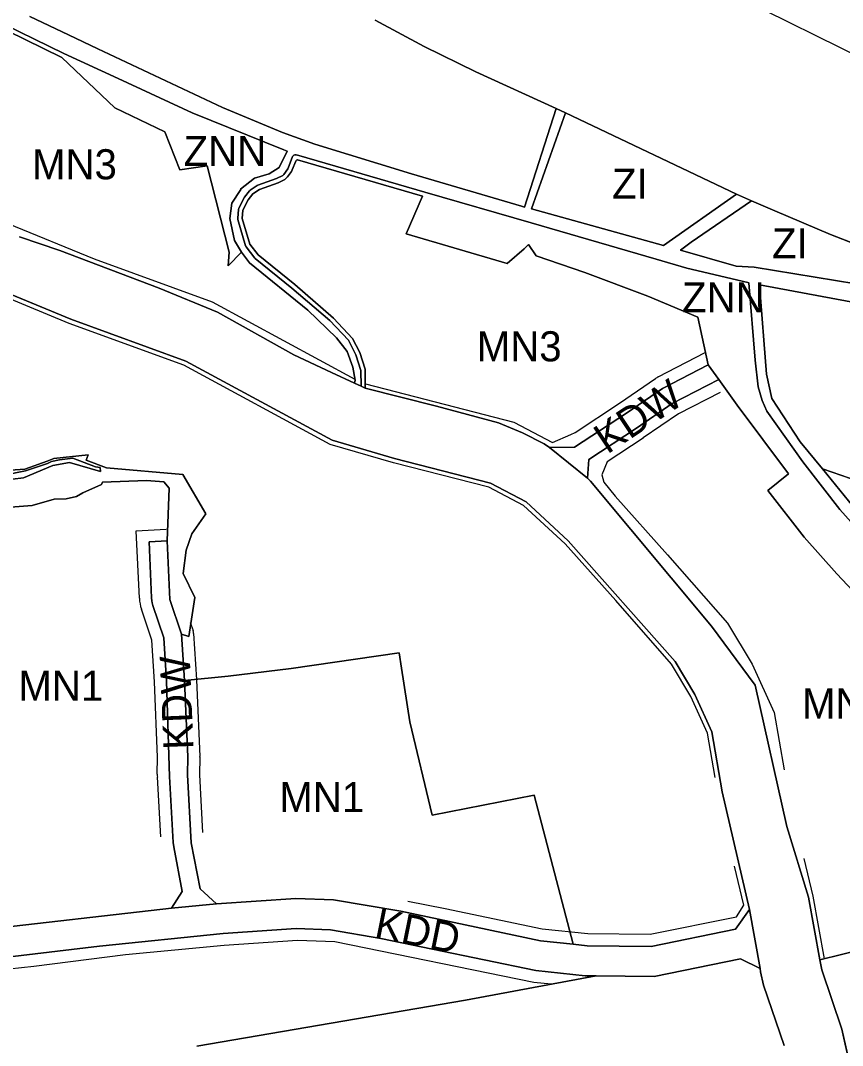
# Model space of a CAD drawing. Extents: x 7417187 to 7419415, y 5539178 to 5540826.
# Drawn here: x 7417955.3 to 7418228.7, y 5540197.8 to 5540538.4 of the extents above; entities that cross this region are included whole.
import ezdxf

# ---------------------------------------------------------------- set-up
doc = ezdxf.new("R2010")
doc.units = 0
for name, color, linetype in [('linie_rozgraniczajace', 7, 'Continuous'), ('linie_zabudowy_nieprzekraczalne', 7, 'Continuous'), ('linie_zabudowy_obowiazujace', 7, 'Continuous'), ('oznaczenia_przeznaczen', 7, 'Continuous')]:
    doc.layers.add(name, color=color, linetype=linetype)

msp = doc.modelspace()

# ---------------------------------------------------------------- linework, layer by layer
at = {"layer": 'linie_rozgraniczajace'}
for p, q in [((7418184.51, 5540550.92), (7418276.66, 5540505.27)), ((7418089.52, 5540529.78), (7418073.23, 5540538.56)), ((7418106.7, 5540521.4), (7418089.52, 5540529.78)), ((7418133.47, 5540509.15), (7418106.7, 5540521.4)), ((7418136.49, 5540507.76), (7418133.47, 5540509.15)), ((7418193.46, 5540480.73), (7418136.49, 5540507.76)), ((7418198.39, 5540478.49), (7418193.46, 5540480.73)), ((7418206.14, 5540475.18), (7418198.39, 5540478.49)), ((7418224.72, 5540467.32), (7418206.14, 5540475.18)), ((7417954.91, 5540466.53), (7417968.32, 5540461.96)), ((7418250.22, 5540457.36), (7418224.72, 5540467.32)), ((7417968.32, 5540461.96), (7418001.44, 5540449.44)), ((7417972.03, 5540439.13), (7417941.88, 5540451.55)), ((7418001.44, 5540449.44), (7418020.76, 5540441.54)), ((7418203.41, 5540420.94), (7418201.06, 5540450.58)), ((7418201.06, 5540450.58), (7418231.46, 5540444.97)), ((7418010.24, 5540425.25), (7417972.03, 5540439.13)), ((7418020.76, 5540441.54), (7418046.17, 5540427.29)), ((7418046.17, 5540427.29), (7418058.73, 5540421.49)), ((7418058.9, 5540398.92), (7418010.24, 5540425.25)), ((7418058.73, 5540421.49), (7418066.38, 5540417.89)), ((7418205.11, 5540412.77), (7418203.41, 5540420.94)), ((7418066.38, 5540417.89), (7418068.6, 5540416.85)), ((7418068.6, 5540416.85), (7418069.96, 5540416.21)), ((7418069.96, 5540416.21), (7418093.68, 5540410.23)), ((7418214.63, 5540398.45), (7418205.11, 5540412.77)), ((7418093.68, 5540410.23), (7418114.25, 5540404.75)), ((7418114.25, 5540404.75), (7418122.23, 5540401.34)), ((7418079.69, 5540392.91), (7418058.9, 5540398.92)), ((7418122.23, 5540401.34), (7418129.46, 5540397.73)), ((7418221.99, 5540389.44), (7418214.63, 5540398.45)), ((7418129.46, 5540397.73), (7418131.26, 5540396.56)), ((7418131.26, 5540396.56), (7418143.87, 5540386.28)), ((7418111.56, 5540384.71), (7418079.69, 5540392.91)), ((7418568.33, 5540270.22), (7418221.99, 5540389.44)), ((7418123.42, 5540378.5), (7418111.56, 5540384.71)), ((7418143.87, 5540386.28), (7418144.87, 5540385.36)), ((7418144.87, 5540385.36), (7418185.06, 5540337.16)), ((7418137.46, 5540365.56), (7418123.42, 5540378.5)), ((7418172.97, 5540325.41), (7418137.46, 5540365.56)), ((7418185.06, 5540337.16), (7418199.57, 5540317.59)), ((7418179.58, 5540314.47), (7418172.97, 5540325.41)), ((7418199.57, 5540317.59), (7418210.2, 5540270.52)), ((7418185.22, 5540302.05), (7418179.58, 5540314.47)), ((7418188.69, 5540282.1), (7418185.22, 5540302.05)), ((7418197.7, 5540242.96), (7418188.69, 5540282.1)), ((7418210.2, 5540270.52), (7418217.35, 5540247.1)), ((7418217.35, 5540247.1), (7418221.14, 5540226.27)), ((7418201.23, 5540223.35), (7418197.7, 5540242.96)), ((7418221.14, 5540226.27), (7418221.74, 5540222.95)), ((7418201.42, 5540222.28), (7418201.23, 5540223.35)), ((7418202.33, 5540217.9), (7418201.42, 5540222.28)), ((7418221.74, 5540222.95), (7418228.49, 5540203.2)), ((7418209.21, 5540197.77), (7418202.33, 5540217.9)), ((7418228.49, 5540203.2), (7418234.02, 5540178.42))]:
    msp.add_line(p, q, dxfattribs=at)
for points in [[(7417945.14, 5540539.44), (7417969.74, 5540527.46), (7417987.79, 5540519.1), (7418012.43, 5540507.77), (7418042.85, 5540495.44), (7418043.98, 5540494.99), (7418041.28, 5540489.53), (7418037.97, 5540487.48), (7418033.07, 5540486), (7418028.48, 5540482.4), (7418028.54, 5540482.27), (7418025.59, 5540477.67), (7418024.93, 5540472.63), (7418026.44, 5540465.3), (7418028.76, 5540461.43), (7418024.37, 5540456.87), (7418024.64, 5540461.41), (7418017.37, 5540490.07), (7418008.26, 5540488.82), (7418003.24, 5540501.47), (7417986.61, 5540509.43), (7417969.09, 5540526.11), (7417944.77, 5540538.03), (7417931.33, 5540544.79)], [(7417944.77, 5540538.03), (7417969.09, 5540526.11), (7417986.61, 5540509.43), (7418003.24, 5540501.47), (7418008.26, 5540488.82), (7418017.37, 5540490.07), (7418024.64, 5540461.41), (7418024.37, 5540456.87), (7418028.76, 5540461.43), (7418031.49, 5540457.9), (7418050.88, 5540442.16), (7418060.36, 5540432.97), (7418063.92, 5540428.39), (7418065.8, 5540423.21), (7418066.58, 5540418.89), (7418066.38, 5540417.89), (7418058.73, 5540421.49), (7418046.17, 5540427.29), (7418020.76, 5540441.54), (7418001.44, 5540449.44), (7417968.32, 5540461.96), (7417954.91, 5540466.53)], [(7418237.98, 5540364.53), (7418227.82, 5540375.89), (7418215.42, 5540391.72), (7418203.51, 5540408.65), (7418201.91, 5540412.14), (7418200.64, 5540416.69), (7418199.58, 5540425.52), (7418197.49, 5540451.24), (7418197.18, 5540451.32), (7418176.94, 5540456.17), (7418166.7, 5540459.13), (7418125.11, 5540471.15), (7418089.75, 5540481.34), (7418047.83, 5540493.52), (7418047, 5540493.76), (7418046.77, 5540493.8), (7418046.51, 5540493.78), (7418046.22, 5540493.67), (7418046, 5540493.49), (7418045.88, 5540493.33), (7418045.8, 5540493.17), (7418044.27, 5540489.34), (7418044.16, 5540489.14), (7418042.87, 5540487.27), (7418042.8, 5540487.17), (7418042.64, 5540487.03), (7418042.51, 5540486.95), (7418040.47, 5540485.89), (7418034.18, 5540483.69), (7418033.96, 5540483.57), (7418031.63, 5540482.01), (7418031.4, 5540481.8), (7418029.8, 5540479.76), (7418029.69, 5540479.59), (7418027.87, 5540475.95), (7418027.79, 5540475.73), (7418027.77, 5540475.58), (7418027.53, 5540472.69), (7418027.53, 5540472.48), (7418027.56, 5540472.32), (7418030.17, 5540463.59), (7418030.2, 5540463.5), (7418030.23, 5540463.42), (7418030.28, 5540463.33), (7418030.34, 5540463.26), (7418033.27, 5540459.48), (7418033.38, 5540459.37), (7418045.55, 5540449.47), (7418058.12, 5540438.7), (7418064.36, 5540432.18), (7418066.85, 5540427.35), (7418068.43, 5540422.14), (7418068.6, 5540416.85), (7418066.38, 5540417.89), (7418066.58, 5540418.89), (7418065.8, 5540423.21), (7418063.92, 5540428.39), (7418060.36, 5540432.97), (7418050.88, 5540442.16), (7418031.49, 5540457.9), (7418028.76, 5540461.43), (7418026.44, 5540465.3), (7418024.93, 5540472.63), (7418025.59, 5540477.67), (7418028.54, 5540482.27), (7418028.48, 5540482.4), (7418033.07, 5540486), (7418037.97, 5540487.48), (7418041.28, 5540489.53), (7418043.98, 5540494.99), (7418042.85, 5540495.44), (7418012.43, 5540507.77), (7417987.79, 5540519.1), (7417969.74, 5540527.46), (7417945.14, 5540539.44)], [(7417958.44, 5540539.73), (7417971.26, 5540533.63), (7417981.02, 5540529.03), (7418022.49, 5540509.53), (7418042.39, 5540501.23), (7418053.23, 5540497.36), (7418085.3, 5540487.44), (7418121.92, 5540476.69), (7418122.9, 5540476.44), (7418133.47, 5540509.15), (7418136.49, 5540507.76), (7418125.23, 5540475.82), (7418169.18, 5540463.68), (7418193.46, 5540480.73), (7418198.39, 5540478.49), (7418178.36, 5540464.75), (7418174.76, 5540462.14), (7418193.33, 5540456.73), (7418199.26, 5540456.48), (7418233.05, 5540450.86)], [(7418073.23, 5540538.56), (7418089.52, 5540529.78), (7418106.7, 5540521.4), (7418133.47, 5540509.15), (7418122.9, 5540476.44), (7418121.92, 5540476.69), (7418085.3, 5540487.44), (7418053.23, 5540497.36), (7418042.39, 5540501.23), (7418022.49, 5540509.53), (7417981.02, 5540529.03), (7417971.26, 5540533.63), (7417958.44, 5540539.73)], [(7418253.06, 5540326.64), (7418226.81, 5540354.53), (7418215.96, 5540366.69), (7418203.79, 5540382.24), (7418210.66, 5540387.82), (7418193.67, 5540410.56), (7418187.52, 5540419.09), (7418184, 5540424.02), (7418180.55, 5540439.82), (7418163.87, 5540446.84), (7418143, 5540454.69), (7418126.77, 5540460.16), (7418124.24, 5540463.97), (7418122.74, 5540462.55), (7418117.16, 5540457.62), (7418083.59, 5540467.54), (7418088.97, 5540480.04), (7418047.41, 5540492.08), (7418047.25, 5540492.09), (7418047.07, 5540492.02), (7418046.92, 5540491.89), (7418046.83, 5540491.71), (7418045.66, 5540488.78), (7418045.4, 5540488.29), (7418044.11, 5540486.42), (7418043.2, 5540485.61), (7418041.16, 5540484.56), (7418040.96, 5540484.47), (7418034.74, 5540482.3), (7418032.53, 5540480.81), (7418031.01, 5540478.87), (7418029.26, 5540475.36), (7418029.03, 5540472.66), (7418031.58, 5540464.1), (7418034.37, 5540460.51), (7418046.5, 5540450.64), (7418059.43, 5540439.55), (7418065.75, 5540432.76), (7418068.19, 5540428.04), (7418069.87, 5540422.58), (7418069.93, 5540422.19), (7418069.96, 5540416.21), (7418068.6, 5540416.85), (7418068.43, 5540422.14), (7418066.85, 5540427.35), (7418064.36, 5540432.18), (7418058.12, 5540438.7), (7418045.55, 5540449.47), (7418033.38, 5540459.37), (7418033.27, 5540459.48), (7418030.34, 5540463.26), (7418030.28, 5540463.33), (7418030.23, 5540463.42), (7418030.2, 5540463.5), (7418030.17, 5540463.59), (7418027.56, 5540472.32), (7418027.53, 5540472.48), (7418027.53, 5540472.69), (7418027.77, 5540475.58), (7418027.79, 5540475.73), (7418027.87, 5540475.95), (7418029.69, 5540479.59), (7418029.8, 5540479.76), (7418031.4, 5540481.8), (7418031.63, 5540482.01), (7418033.96, 5540483.57), (7418034.18, 5540483.69), (7418040.47, 5540485.89), (7418042.51, 5540486.95), (7418042.64, 5540487.03), (7418042.8, 5540487.17), (7418042.87, 5540487.27), (7418044.16, 5540489.14), (7418044.27, 5540489.34), (7418045.8, 5540493.17), (7418045.88, 5540493.33), (7418046, 5540493.49), (7418046.22, 5540493.67), (7418046.51, 5540493.78), (7418046.77, 5540493.8), (7418047, 5540493.76), (7418047.83, 5540493.52), (7418089.75, 5540481.34), (7418125.11, 5540471.15), (7418166.7, 5540459.13), (7418176.94, 5540456.17), (7418197.18, 5540451.32), (7418197.49, 5540451.24), (7418199.58, 5540425.52), (7418200.64, 5540416.69), (7418201.91, 5540412.14), (7418203.51, 5540408.65), (7418215.42, 5540391.72), (7418227.82, 5540375.89), (7418237.98, 5540364.53)], [(7417941.88, 5540451.55), (7417972.03, 5540439.13), (7418010.24, 5540425.25), (7418058.9, 5540398.92), (7418079.69, 5540392.91), (7418111.56, 5540384.71), (7418123.42, 5540378.5), (7418137.46, 5540365.56), (7418172.97, 5540325.41), (7418179.58, 5540314.47), (7418185.22, 5540302.05), (7418188.69, 5540282.1), (7418197.7, 5540242.96), (7418193.07, 5540236.44), (7418165.06, 5540230.74), (7418143.69, 5540230.97), (7418139.13, 5540231.45), (7418126.13, 5540281), (7418092.21, 5540274.34), (7418084.77, 5540305.35), (7418082.04, 5540323.19), (7418081.27, 5540328.34), (7418045.29, 5540323.12), (7418024.34, 5540320.55), (7418009.86, 5540319.08), (7418008.88, 5540334.46), (7418011.3, 5540333.72), (7418013.28, 5540346.63), (7418009.37, 5540354.65), (7418010.34, 5540362.43), (7418012.27, 5540367.82), (7418016.98, 5540374.46), (7418009.32, 5540387.6), (7417983.86, 5540389.74), (7417977.17, 5540392.31), (7417977.79, 5540394.13), (7417966.38, 5540392.86), (7417964.16, 5540391.99), (7417956.78, 5540389.28), (7417948.8, 5540388.78)], [(7418231.46, 5540444.97), (7418201.06, 5540450.58), (7418203.41, 5540420.94), (7418205.11, 5540412.77), (7418214.63, 5540398.45), (7418221.99, 5540389.44), (7418235.03, 5540373.5)], [(7418235.5, 5540229.77), (7418221.14, 5540226.27), (7418217.35, 5540247.1), (7418210.2, 5540270.52), (7418199.57, 5540317.59), (7418185.06, 5540337.16), (7418144.87, 5540385.36), (7418143.87, 5540386.28), (7418144.29, 5540392.55), (7418160.16, 5540402.99), (7418172.05, 5540411.13), (7418187.52, 5540419.09), (7418193.67, 5540410.56), (7418210.66, 5540387.82), (7418203.79, 5540382.24), (7418215.96, 5540366.69), (7418226.81, 5540354.53), (7418253.06, 5540326.64)], [(7417948.8, 5540388.78), (7417956.78, 5540389.28), (7417964.16, 5540391.99), (7417966.38, 5540392.86), (7417977.79, 5540394.13), (7417977.17, 5540392.31), (7417983.86, 5540389.74), (7418009.32, 5540387.6), (7418016.98, 5540374.46), (7418012.27, 5540367.82), (7418010.34, 5540362.43), (7418009.37, 5540354.65), (7418013.28, 5540346.63), (7418011.3, 5540333.72), (7418008.88, 5540334.46), (7418004.97, 5540345.99), (7418004.08, 5540365.45), (7418004.77, 5540383), (7418002.97, 5540385.08), (7417997.21, 5540385.56), (7417982.61, 5540384.97), (7417982.26, 5540384.26), (7417976.05, 5540381.43), (7417973.97, 5540380.19), (7417970.52, 5540379.47), (7417966.47, 5540379.3), (7417959.21, 5540377.27), (7417950.55, 5540376.53)], [(7417949.83, 5540387.35), (7417956.94, 5540388.72), (7417964.23, 5540391.24), (7417965.64, 5540391.82), (7417968.27, 5540392.44), (7417972.69, 5540392.96), (7417980.27, 5540390.05), (7417981.75, 5540389.92), (7417981.88, 5540388.54), (7417971.57, 5540391.49), (7417966.02, 5540390.49), (7417956.24, 5540386.4), (7417949.01, 5540385.55)], [(7417949.01, 5540385.55), (7417956.24, 5540386.4), (7417966.02, 5540390.49), (7417971.57, 5540391.49), (7417981.88, 5540388.54), (7417981.75, 5540389.92), (7417980.27, 5540390.05), (7417972.69, 5540392.96), (7417968.27, 5540392.44), (7417965.64, 5540391.82), (7417964.23, 5540391.24), (7417956.94, 5540388.72), (7417949.83, 5540387.35)], [(7418235.03, 5540373.5), (7418221.99, 5540389.44), (7418568.33, 5540270.22)], [(7417950.55, 5540376.53), (7417959.21, 5540377.27), (7417966.47, 5540379.3), (7417970.52, 5540379.47), (7417973.97, 5540380.19), (7417976.05, 5540381.43), (7417982.26, 5540384.26), (7417982.61, 5540384.97), (7417997.21, 5540385.56), (7418002.97, 5540385.08), (7418004.77, 5540383), (7418004.08, 5540365.45), (7417998.07, 5540365.21), (7417998.82, 5540346.59), (7417998.92, 5540345.57), (7417999.06, 5540344.87), (7417999.29, 5540344.07), (7418002.94, 5540333.29), (7418003.86, 5540318.84), (7418004.79, 5540287.17), (7418006.03, 5540265.31), (7418006.26, 5540263.77), (7418009.07, 5540248.98), (7418005.47, 5540243.42), (7417941.39, 5540236.16)], [(7417941.39, 5540236.16), (7418005.47, 5540243.42), (7418020.52, 5540244.86), (7418046.89, 5540246.66), (7418059.4, 5540246.2), (7418081.8, 5540242.41), (7418128.19, 5540232.61), (7418139.13, 5540231.45), (7418143.69, 5540230.97), (7418165.06, 5540230.74), (7418193.07, 5540236.44), (7418197.7, 5540242.96), (7418201.23, 5540223.35), (7418194.77, 5540226.58), (7418166.01, 5540220.73), (7418146.77, 5540220.94), (7418143.11, 5540220.98), (7418126.64, 5540222.72), (7418075.08, 5540233.41), (7418058.38, 5540236.24), (7418046.99, 5540236.65), (7418022.74, 5540235), (7417981.56, 5540230.85), (7417950.9, 5540227.13)], [(7417950.9, 5540227.13), (7417981.56, 5540230.85), (7418022.74, 5540235), (7418046.99, 5540236.65), (7418058.38, 5540236.24), (7418075.08, 5540233.41), (7418126.64, 5540222.72), (7418143.11, 5540220.98), (7418146.77, 5540220.94), (7418103.26, 5540212.86), (7418013.89, 5540197.63)], [(7418234.02, 5540178.42), (7418228.49, 5540203.2), (7418221.74, 5540222.95), (7418221.14, 5540226.27), (7418235.5, 5540229.77)], [(7418013.89, 5540197.63), (7418103.26, 5540212.86), (7418146.77, 5540220.94), (7418166.01, 5540220.73), (7418194.77, 5540226.58), (7418201.23, 5540223.35), (7418201.42, 5540222.28), (7418202.33, 5540217.9), (7418209.21, 5540197.77)]]:
    msp.add_lwpolyline(points, dxfattribs=at)
for points in [[(7418193.46, 5540480.73), (7418169.18, 5540463.68), (7418125.23, 5540475.82), (7418136.49, 5540507.76)], [(7418184, 5540424.02), (7418168.77, 5540416.15), (7418156.79, 5540407.96), (7418139.51, 5540396.59), (7418131.26, 5540396.56), (7418129.46, 5540397.73), (7418122.23, 5540401.34), (7418114.25, 5540404.75), (7418093.68, 5540410.23), (7418069.96, 5540416.21), (7418069.93, 5540422.19), (7418069.87, 5540422.58), (7418068.19, 5540428.04), (7418065.75, 5540432.76), (7418059.43, 5540439.55), (7418046.5, 5540450.64), (7418034.37, 5540460.51), (7418031.58, 5540464.1), (7418029.03, 5540472.66), (7418029.26, 5540475.36), (7418031.01, 5540478.87), (7418032.53, 5540480.81), (7418034.74, 5540482.3), (7418040.96, 5540484.47), (7418041.16, 5540484.56), (7418043.2, 5540485.61), (7418044.11, 5540486.42), (7418045.4, 5540488.29), (7418045.66, 5540488.78), (7418046.83, 5540491.71), (7418046.92, 5540491.89), (7418047.07, 5540492.02), (7418047.25, 5540492.09), (7418047.41, 5540492.08), (7418088.97, 5540480.04), (7418083.59, 5540467.54), (7418117.16, 5540457.62), (7418122.74, 5540462.55), (7418124.24, 5540463.97), (7418126.77, 5540460.16), (7418143, 5540454.69), (7418163.87, 5540446.84), (7418180.55, 5540439.82)], [(7418275.89, 5540448.03), (7418272.05, 5540447.47), (7418267.29, 5540447.39), (7418253.23, 5540448.9), (7418233.05, 5540450.86), (7418199.26, 5540456.48), (7418193.33, 5540456.73), (7418174.76, 5540462.14), (7418178.36, 5540464.75), (7418198.39, 5540478.49), (7418206.14, 5540475.18), (7418224.72, 5540467.32), (7418250.22, 5540457.36)], [(7418187.52, 5540419.09), (7418172.05, 5540411.13), (7418160.16, 5540402.99), (7418144.29, 5540392.55), (7418143.87, 5540386.28), (7418131.26, 5540396.56), (7418139.51, 5540396.59), (7418156.79, 5540407.96), (7418168.77, 5540416.15), (7418184, 5540424.02)], [(7418008.88, 5540334.46), (7418009.86, 5540319.08), (7418010.89, 5540293.69), (7418010.78, 5540287.74), (7418012.1, 5540265.14), (7418015.04, 5540249.87), (7418020.52, 5540244.86), (7418005.47, 5540243.42), (7418009.07, 5540248.98), (7418006.26, 5540263.77), (7418006.03, 5540265.31), (7418004.79, 5540287.17), (7418003.86, 5540318.84), (7418002.94, 5540333.29), (7417999.29, 5540344.07), (7417999.06, 5540344.87), (7417998.92, 5540345.57), (7417998.82, 5540346.59), (7417998.07, 5540365.21), (7418004.08, 5540365.45), (7418004.97, 5540345.99)], [(7418139.13, 5540231.45), (7418128.19, 5540232.61), (7418081.8, 5540242.41), (7418059.4, 5540246.2), (7418046.89, 5540246.66), (7418020.52, 5540244.86), (7418015.04, 5540249.87), (7418012.1, 5540265.14), (7418010.78, 5540287.74), (7418010.89, 5540293.69), (7418009.86, 5540319.08), (7418024.34, 5540320.55), (7418045.29, 5540323.12), (7418081.27, 5540328.34), (7418082.04, 5540323.19), (7418084.77, 5540305.35), (7418092.21, 5540274.34), (7418126.13, 5540281)]]:
    msp.add_lwpolyline(points, close=True, dxfattribs=at)
at = {"layer": 'linie_zabudowy_nieprzekraczalne'}
msp.add_line((7418162.42, 5540399.69), (7418162.32, 5540399.63), dxfattribs=at)
for points in [[(7418186.34, 5540286.9), (7418183.78, 5540301.6), (7418178.26, 5540313.77), (7418171.76, 5540324.53), (7418153.24, 5540345.66), (7418136.4, 5540364.51), (7418122.55, 5540377.27), (7418111.02, 5540383.3), (7418079.3, 5540391.47), (7418058.33, 5540397.52), (7418009.62, 5540423.88), (7417971.49, 5540437.73), (7417941.24, 5540450.2), (7417899.2, 5540472.95), (7417859.44, 5540494.09), (7417832.88, 5540506.56), (7417829.33, 5540508.1)], [(7417895.18, 5540501.14), (7417910.07, 5540493.22), (7417951.12, 5540471), (7417979.8, 5540459.18), (7418019.07, 5540444.92), (7418066.51, 5540419.25)], [(7418167.37, 5540419.96), (7418183.02, 5540428.09)], [(7418139.79, 5540401.5), (7418154.55, 5540411.27), (7418166.51, 5540419.45)], [(7418069.99, 5540417.64), (7418119.33, 5540404.91), (7418132.18, 5540398.19)], [(7418188.02, 5540414.85), (7418174.11, 5540407.69), (7418162.42, 5540399.69)], [(7418132.18, 5540398.19), (7418138.36, 5540400.85), (7418139.79, 5540401.5)], [(7418162.32, 5540399.63), (7418150.39, 5540391.72)], [(7418150.39, 5540391.72), (7418148.66, 5540387.47), (7418149.31, 5540384.95), (7418153.06, 5540380.37)], [(7418153.06, 5540380.37), (7418170.46, 5540360.9), (7418190.39, 5540338.16), (7418198.64, 5540324.51), (7418205.94, 5540308.44), (7418209.25, 5540289.36)], [(7418215.84, 5540259.9), (7418218.82, 5540247.41), (7418222.6, 5540226.63)], [(7418195.88, 5540244.48), (7418192.79, 5540257.42)], [(7418084.12, 5540245.75), (7418096.49, 5540243.27), (7418128.81, 5540236.57), (7418143.93, 5540234.97)], [(7418193.38, 5540240.59), (7418195.88, 5540244.48)], [(7418143.93, 5540234.97), (7418164.68, 5540234.74), (7418193.38, 5540240.59)], [(7418047.42, 5540232.67), (7418022.98, 5540231.01)], [(7418059.83, 5540232.26), (7418047.42, 5540232.67)], [(7418126.02, 5540218.77), (7418059.83, 5540232.26)], [(7417990.25, 5540227.91), (7417959.74, 5540224.09)], [(7418022.98, 5540231.01), (7417990.25, 5540227.91)], [(7417959.74, 5540224.09), (7417935.05, 5540221.41)], [(7418131.82, 5540218.16), (7418126.02, 5540218.77)]]:
    msp.add_lwpolyline(points, dxfattribs=at)
msp.add_arc((7418171.69, 5540411.85), 9.2, 118.0285, 124.2901, dxfattribs=at)
at = {"layer": 'linie_zabudowy_obowiazujace'}
msp.add_line((7418013.85, 5540319.41), (7418013.85, 5540319.32), dxfattribs=at)
for points in [[(7417993.78, 5540368.86), (7418003.76, 5540369.41)], [(7417994.83, 5540346.43), (7417993.78, 5540368.86)], [(7418000.78, 5540287.92), (7418000.89, 5540293.58), (7417999.87, 5540318.64), (7417998.99, 5540332.51), (7417995.51, 5540342.79)], [(7418011.77, 5540338.41), (7418012.67, 5540335.75)], [(7418012.88, 5540334.72), (7418013.85, 5540319.41)], [(7418013.85, 5540319.32), (7418014.89, 5540293.85)], [(7418014.89, 5540293.62), (7418014.78, 5540287.7), (7418015.86, 5540268.63)], [(7418001.93, 5540267.09), (7418000.8, 5540286.95)]]:
    msp.add_lwpolyline(points, dxfattribs=at)
for centre, radius, start, end in [((7418007.92, 5540346.99), 13.1, 182.4588, 198.7044), ((7418008.96, 5540334.46), 3.93, 3.8404, 19.2071), ((7418013.5, 5540293.67), 1.39, 357.7259, 7.2532), ((7418012.67, 5540287.68), 11.89, 178.8439, 183.5185)]:
    msp.add_arc(centre, radius, start, end, dxfattribs=at)

# ---------------------------------------------------------------- texts
at = {"layer": 'oznaczenia_przeznaczen'}
for s, p in [('ZNN', (7418009.52, 5540490.05)), ('MN3', (7417959.11, 5540485.64)), ('ZI', (7418152.04, 5540479.21)), ('ZI', (7418205.24, 5540459.4)), ('ZNN', (7418175.29, 5540441.39)), ('MN3', (7418107.01, 5540425.15)), ('MN1', (7417954.57, 5540312.35)), ('MN3', (7418215.18, 5540306.46)), ('MN1', (7418041.36, 5540275.35))]:
    msp.add_text(s, height=10, dxfattribs=at).set_placement(p)
for s, rotation, p in [('KDW', 33.5986, (7418150.4, 5540394.11)), ('KDW', 92.2906, (7418012.83, 5540296.27)), ('KDD', 348.6059, (7418072.61, 5540233.75))]:
    msp.add_text(s, height=10, rotation=rotation, dxfattribs=at).set_placement(p)

doc.saveas('drawing.dxf')
